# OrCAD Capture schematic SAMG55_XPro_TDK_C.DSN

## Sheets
1 Block Diagram: title: Xpro and TDK-Sensor; rev: C; company: TDK (Invensense); note: Block Diagram; note: 1745 Technology Dr.; note: San Jose, CA 95110
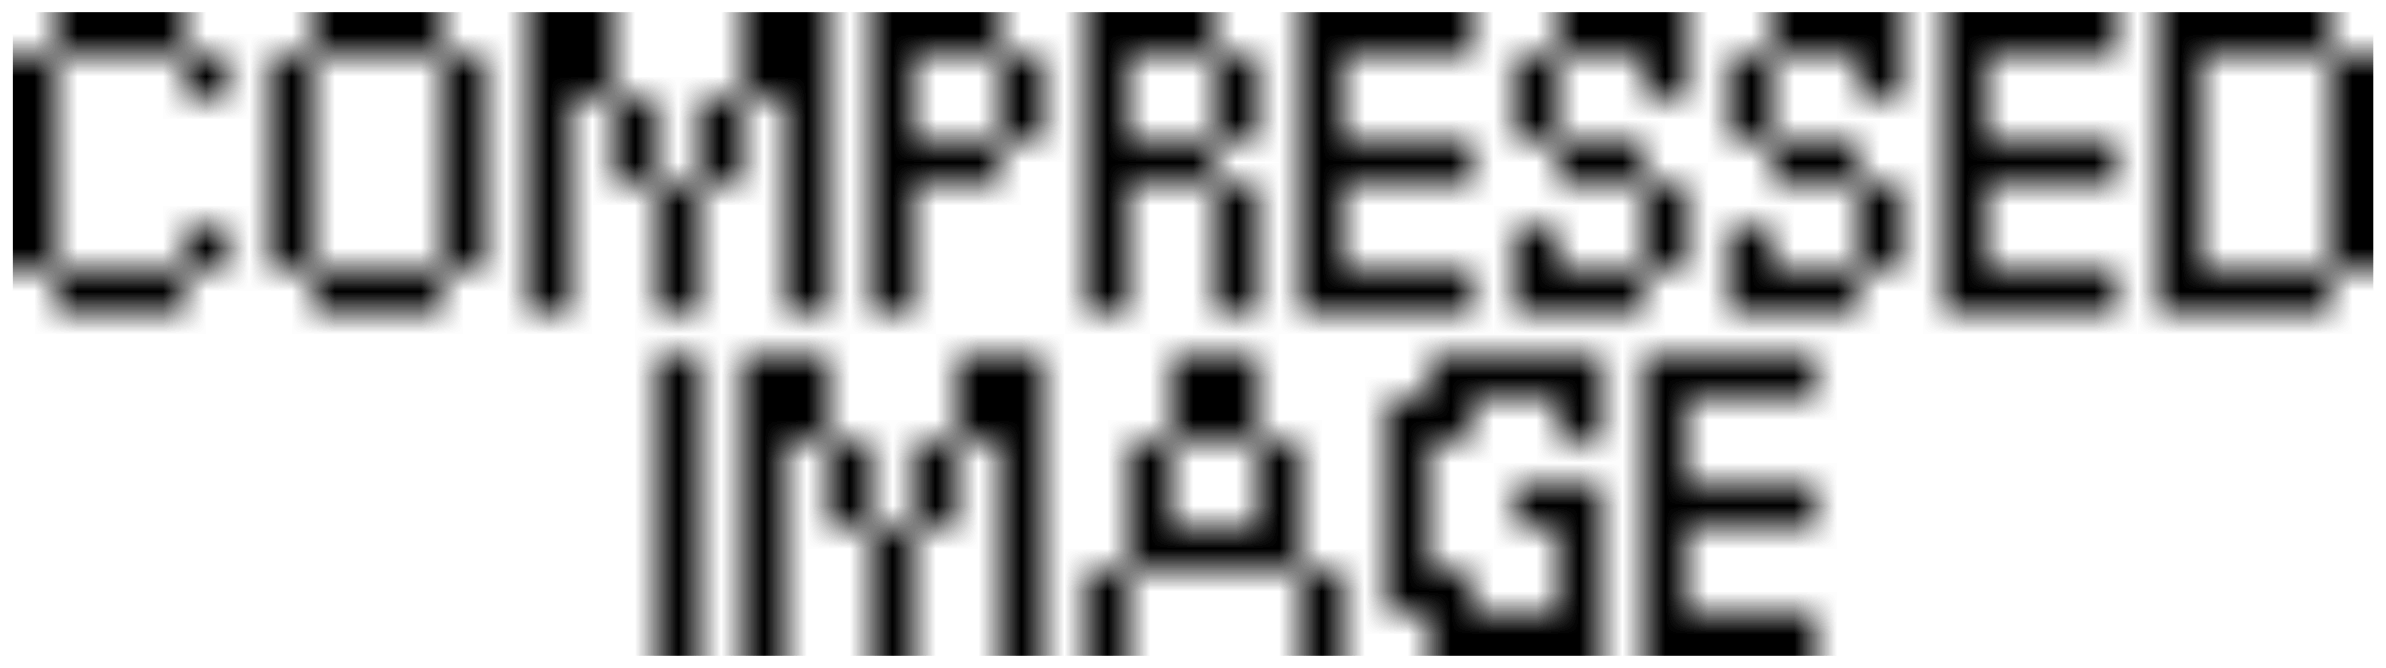
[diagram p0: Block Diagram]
2 TOP: size Custom; note: Top
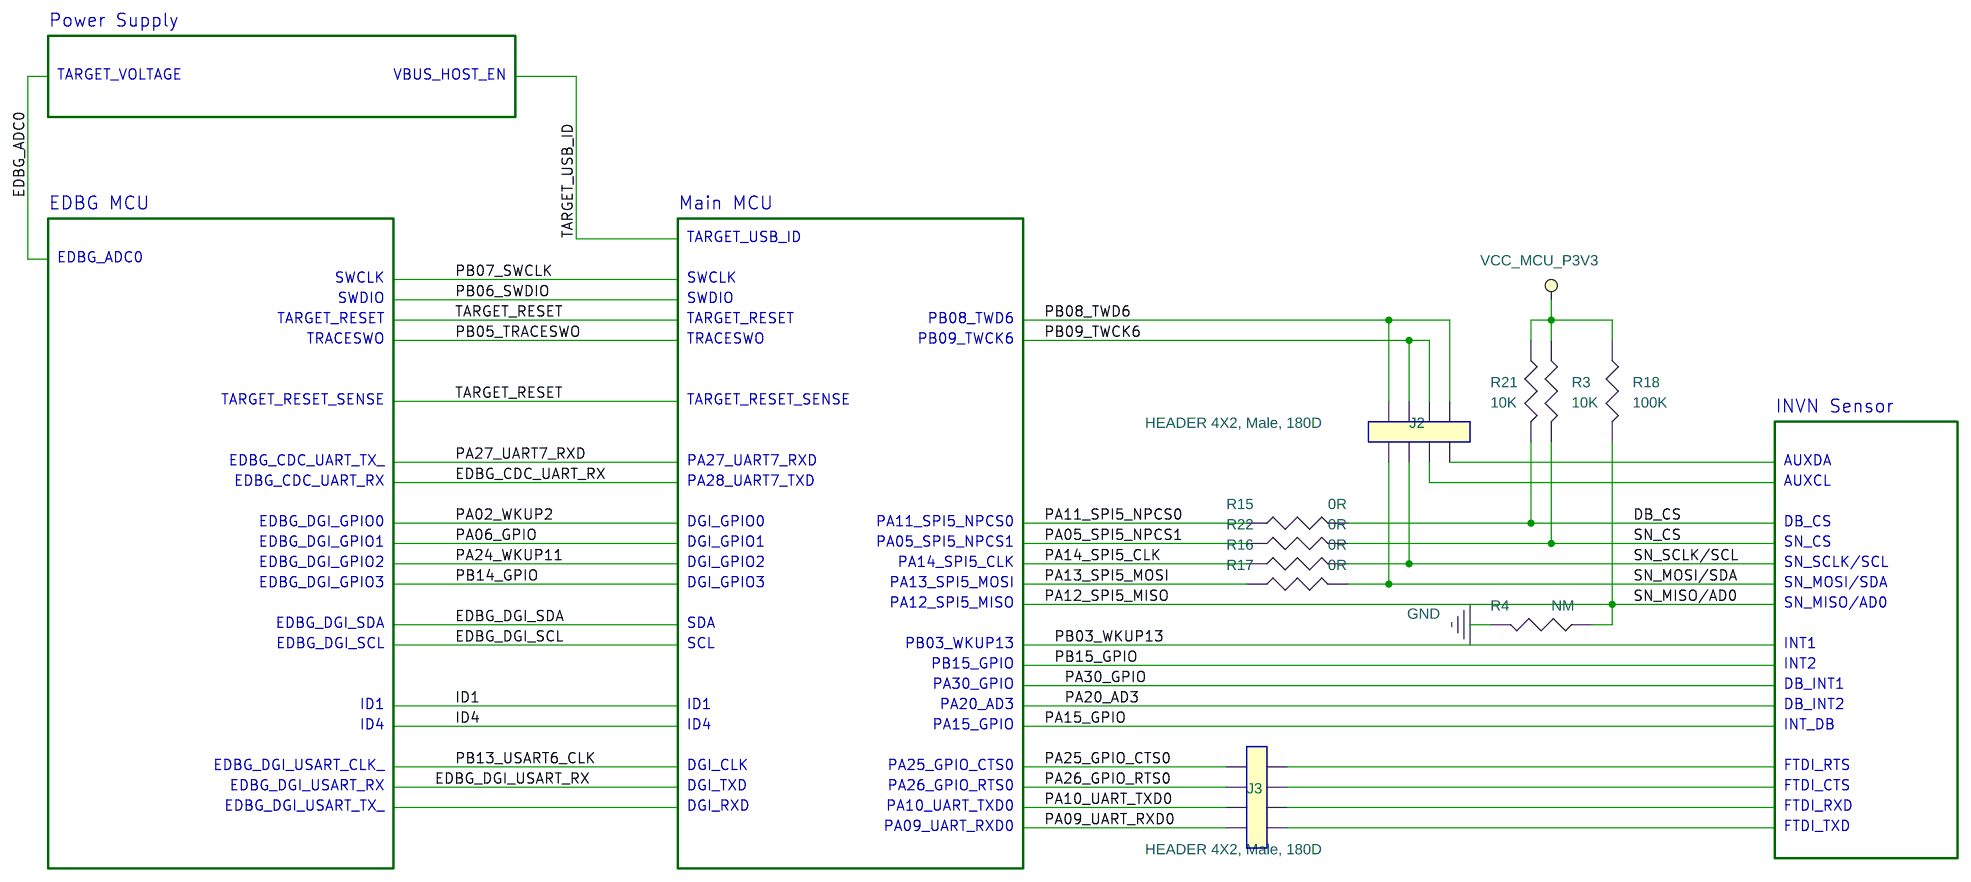
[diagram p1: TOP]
3 EDBG MCU: size Custom; note: EDBG (Embedded Debugger); block EDBG MCU
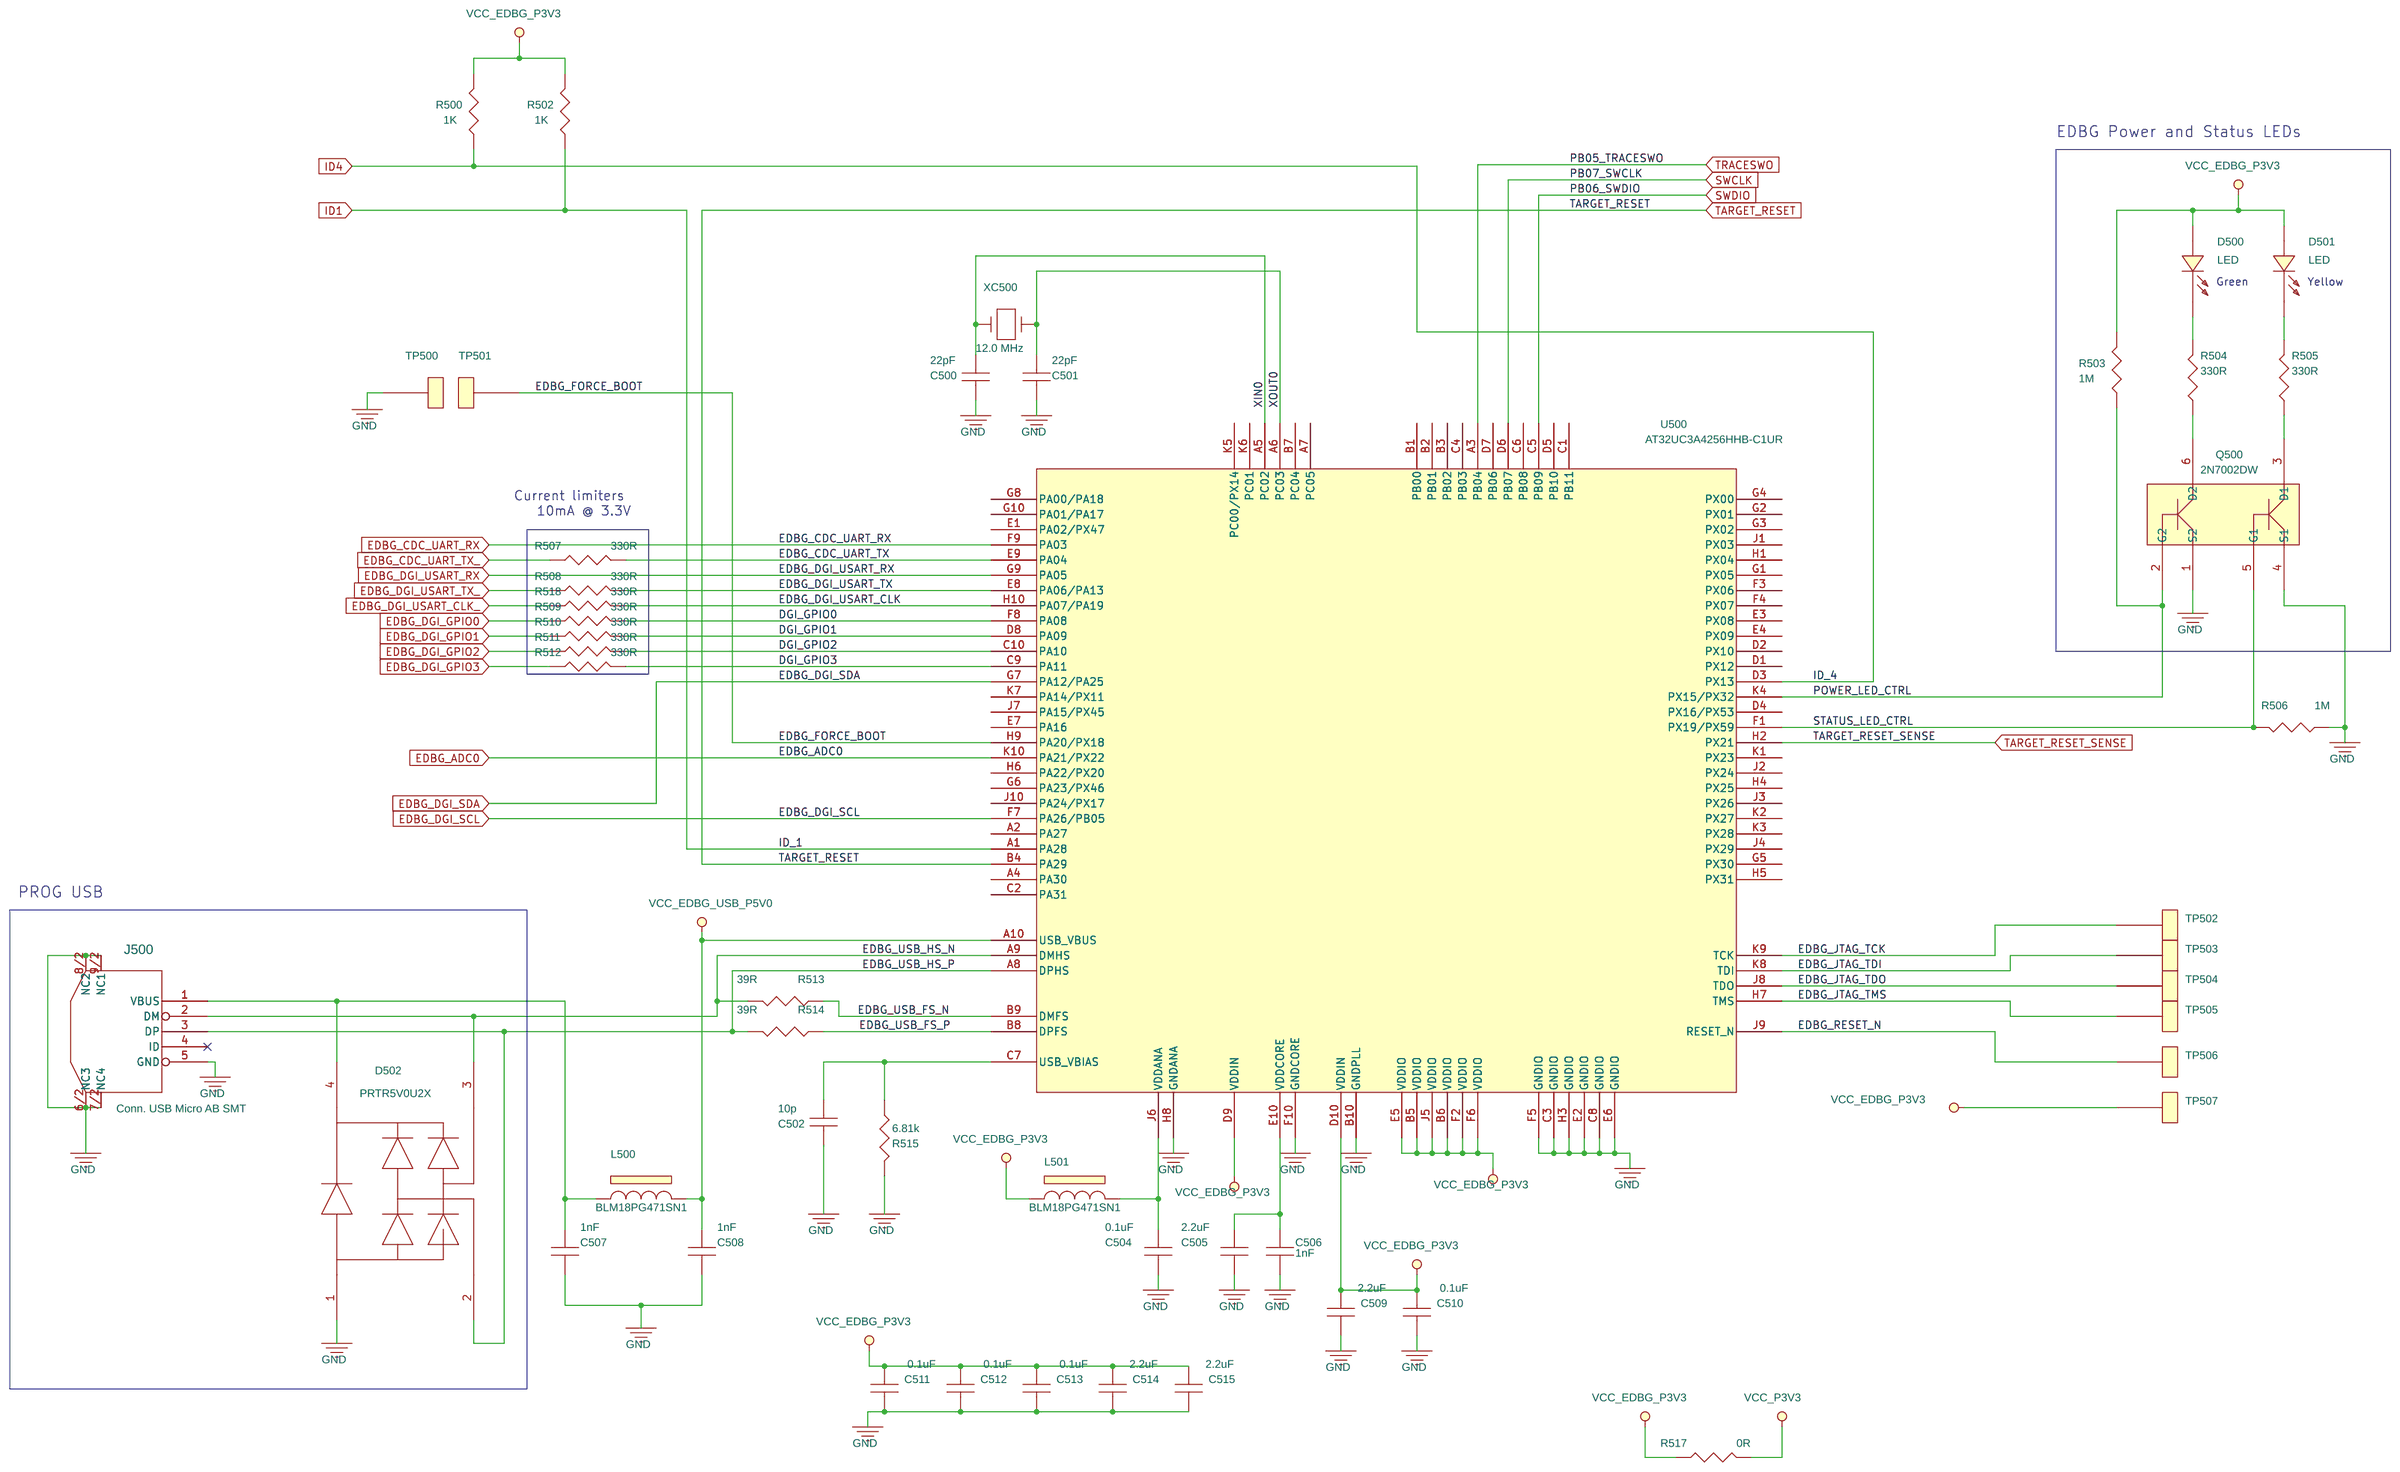
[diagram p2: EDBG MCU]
4 INVN Sensor: size Custom; note: TDK (InvenSense Sensor); block INVN Sensor
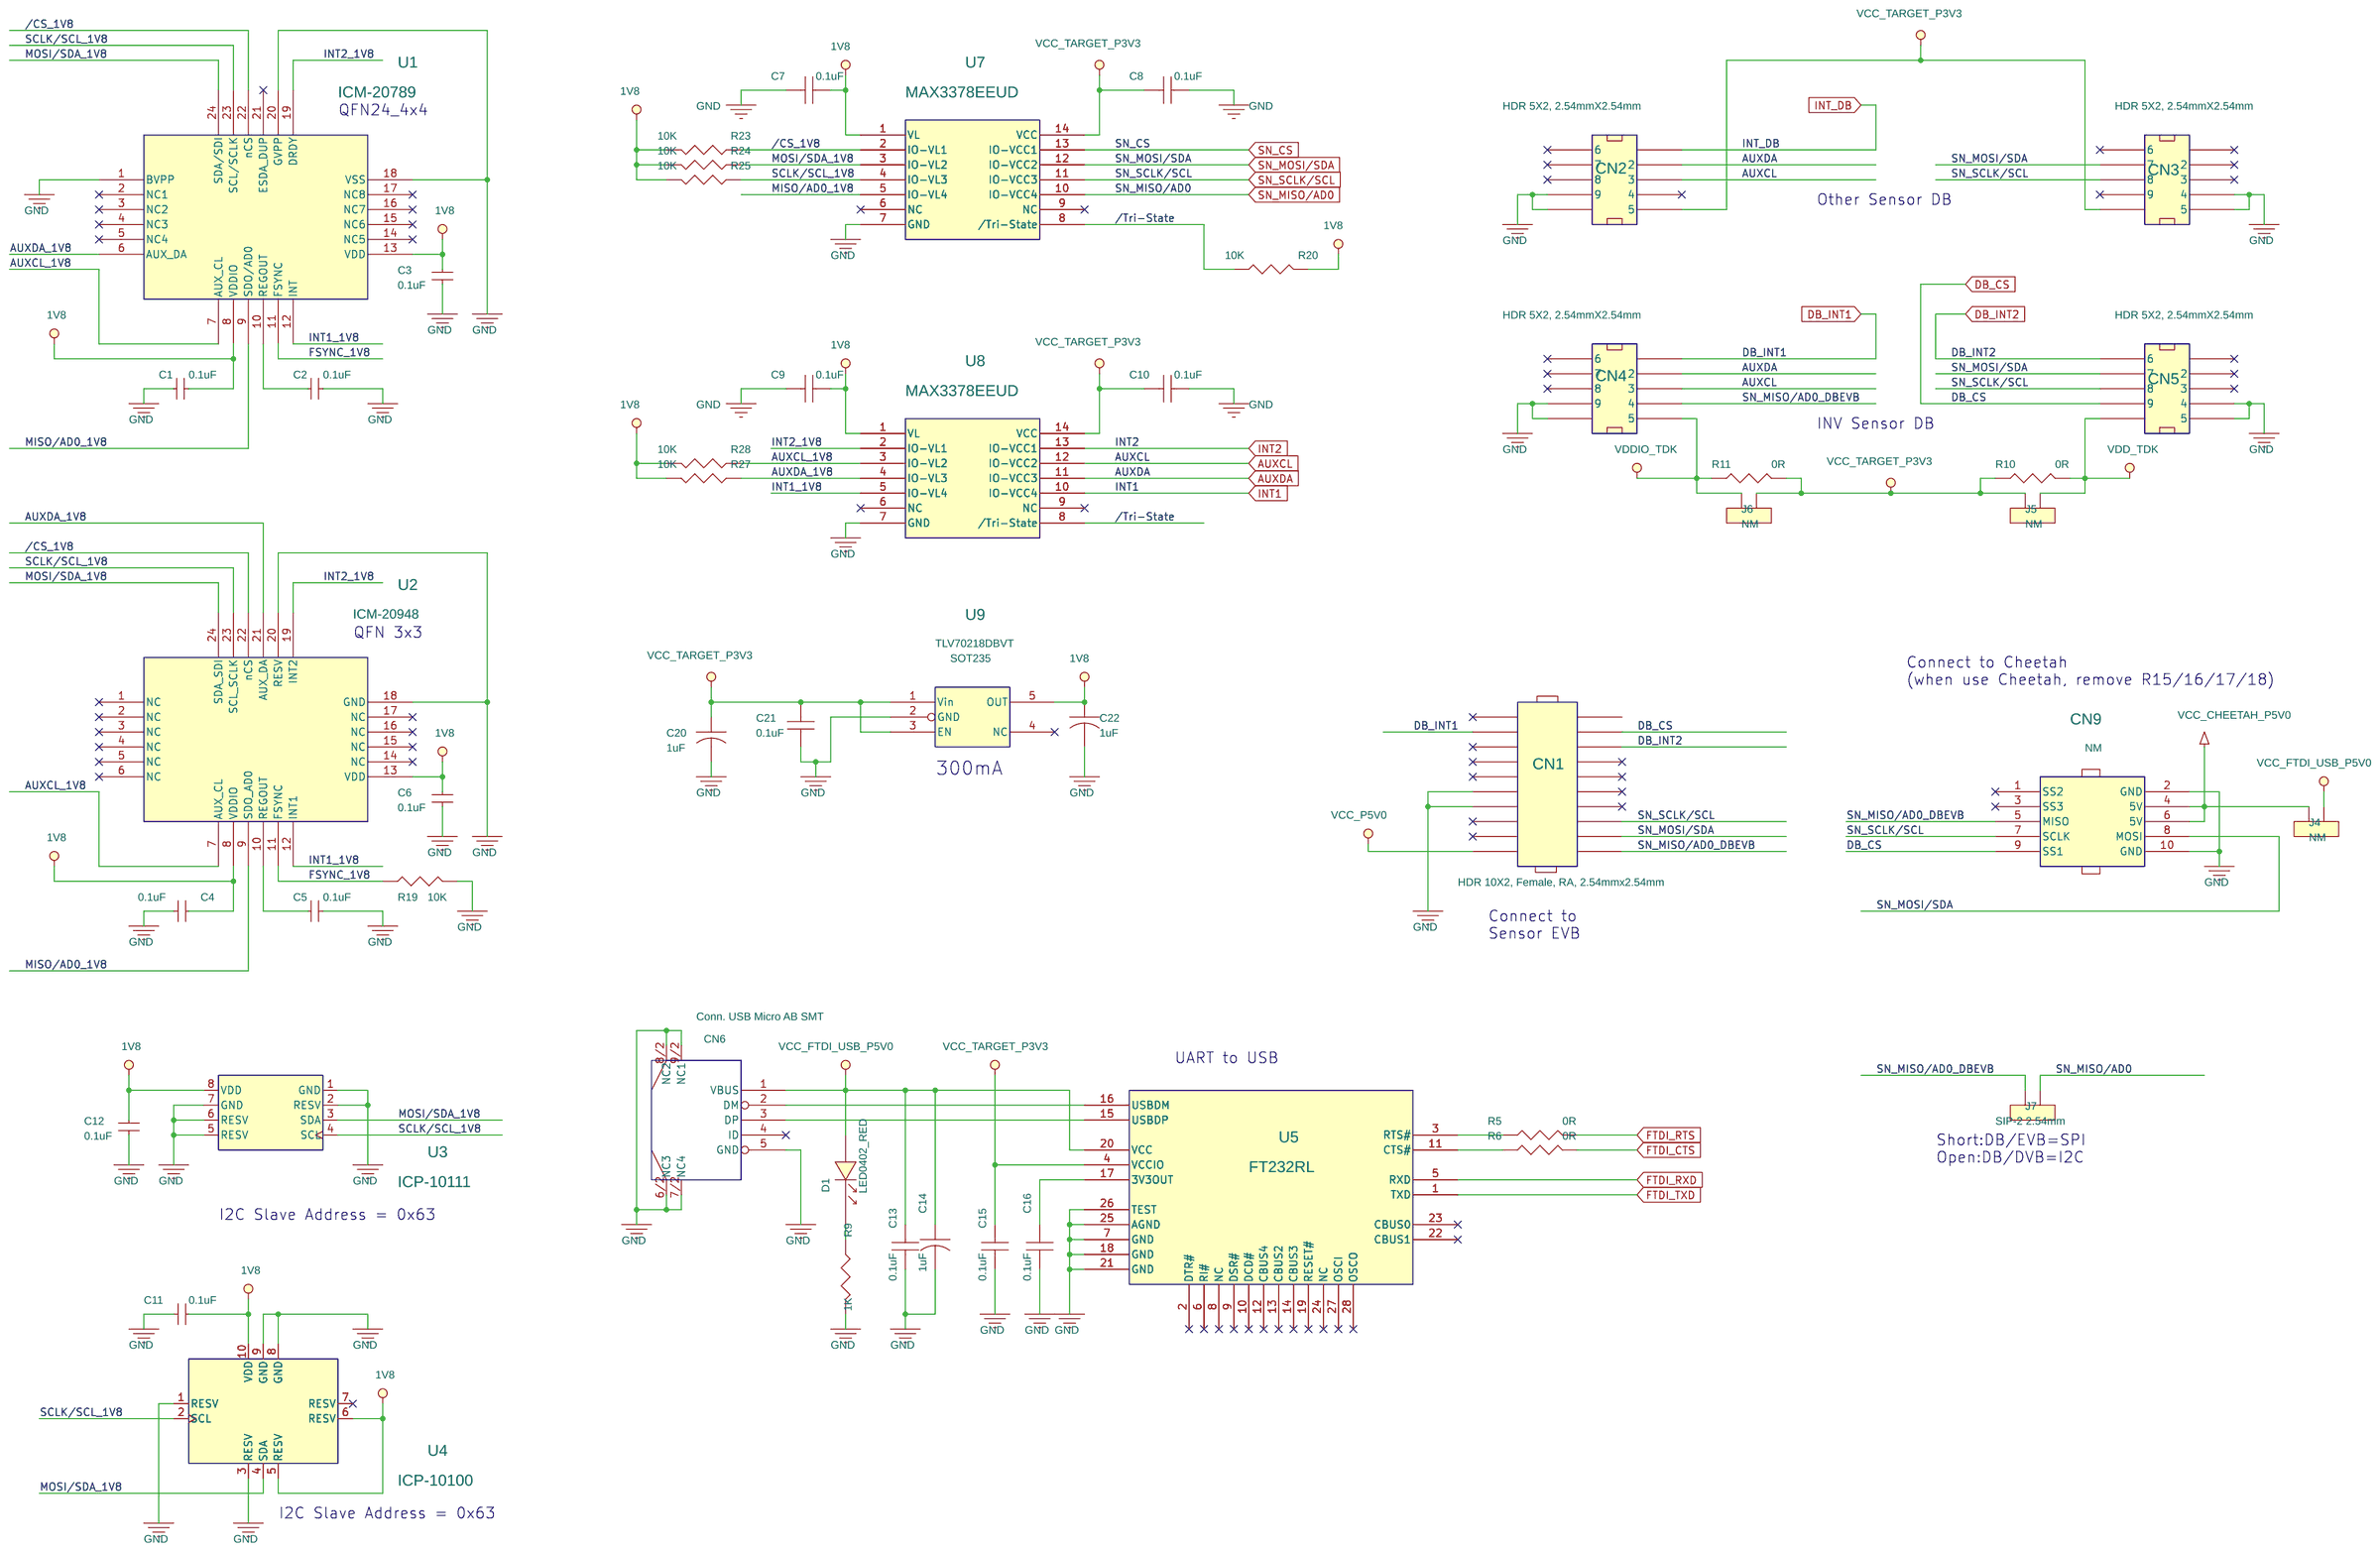
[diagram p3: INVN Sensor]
5 Main MCU: size Custom; note: Main MCU; block Main MCU
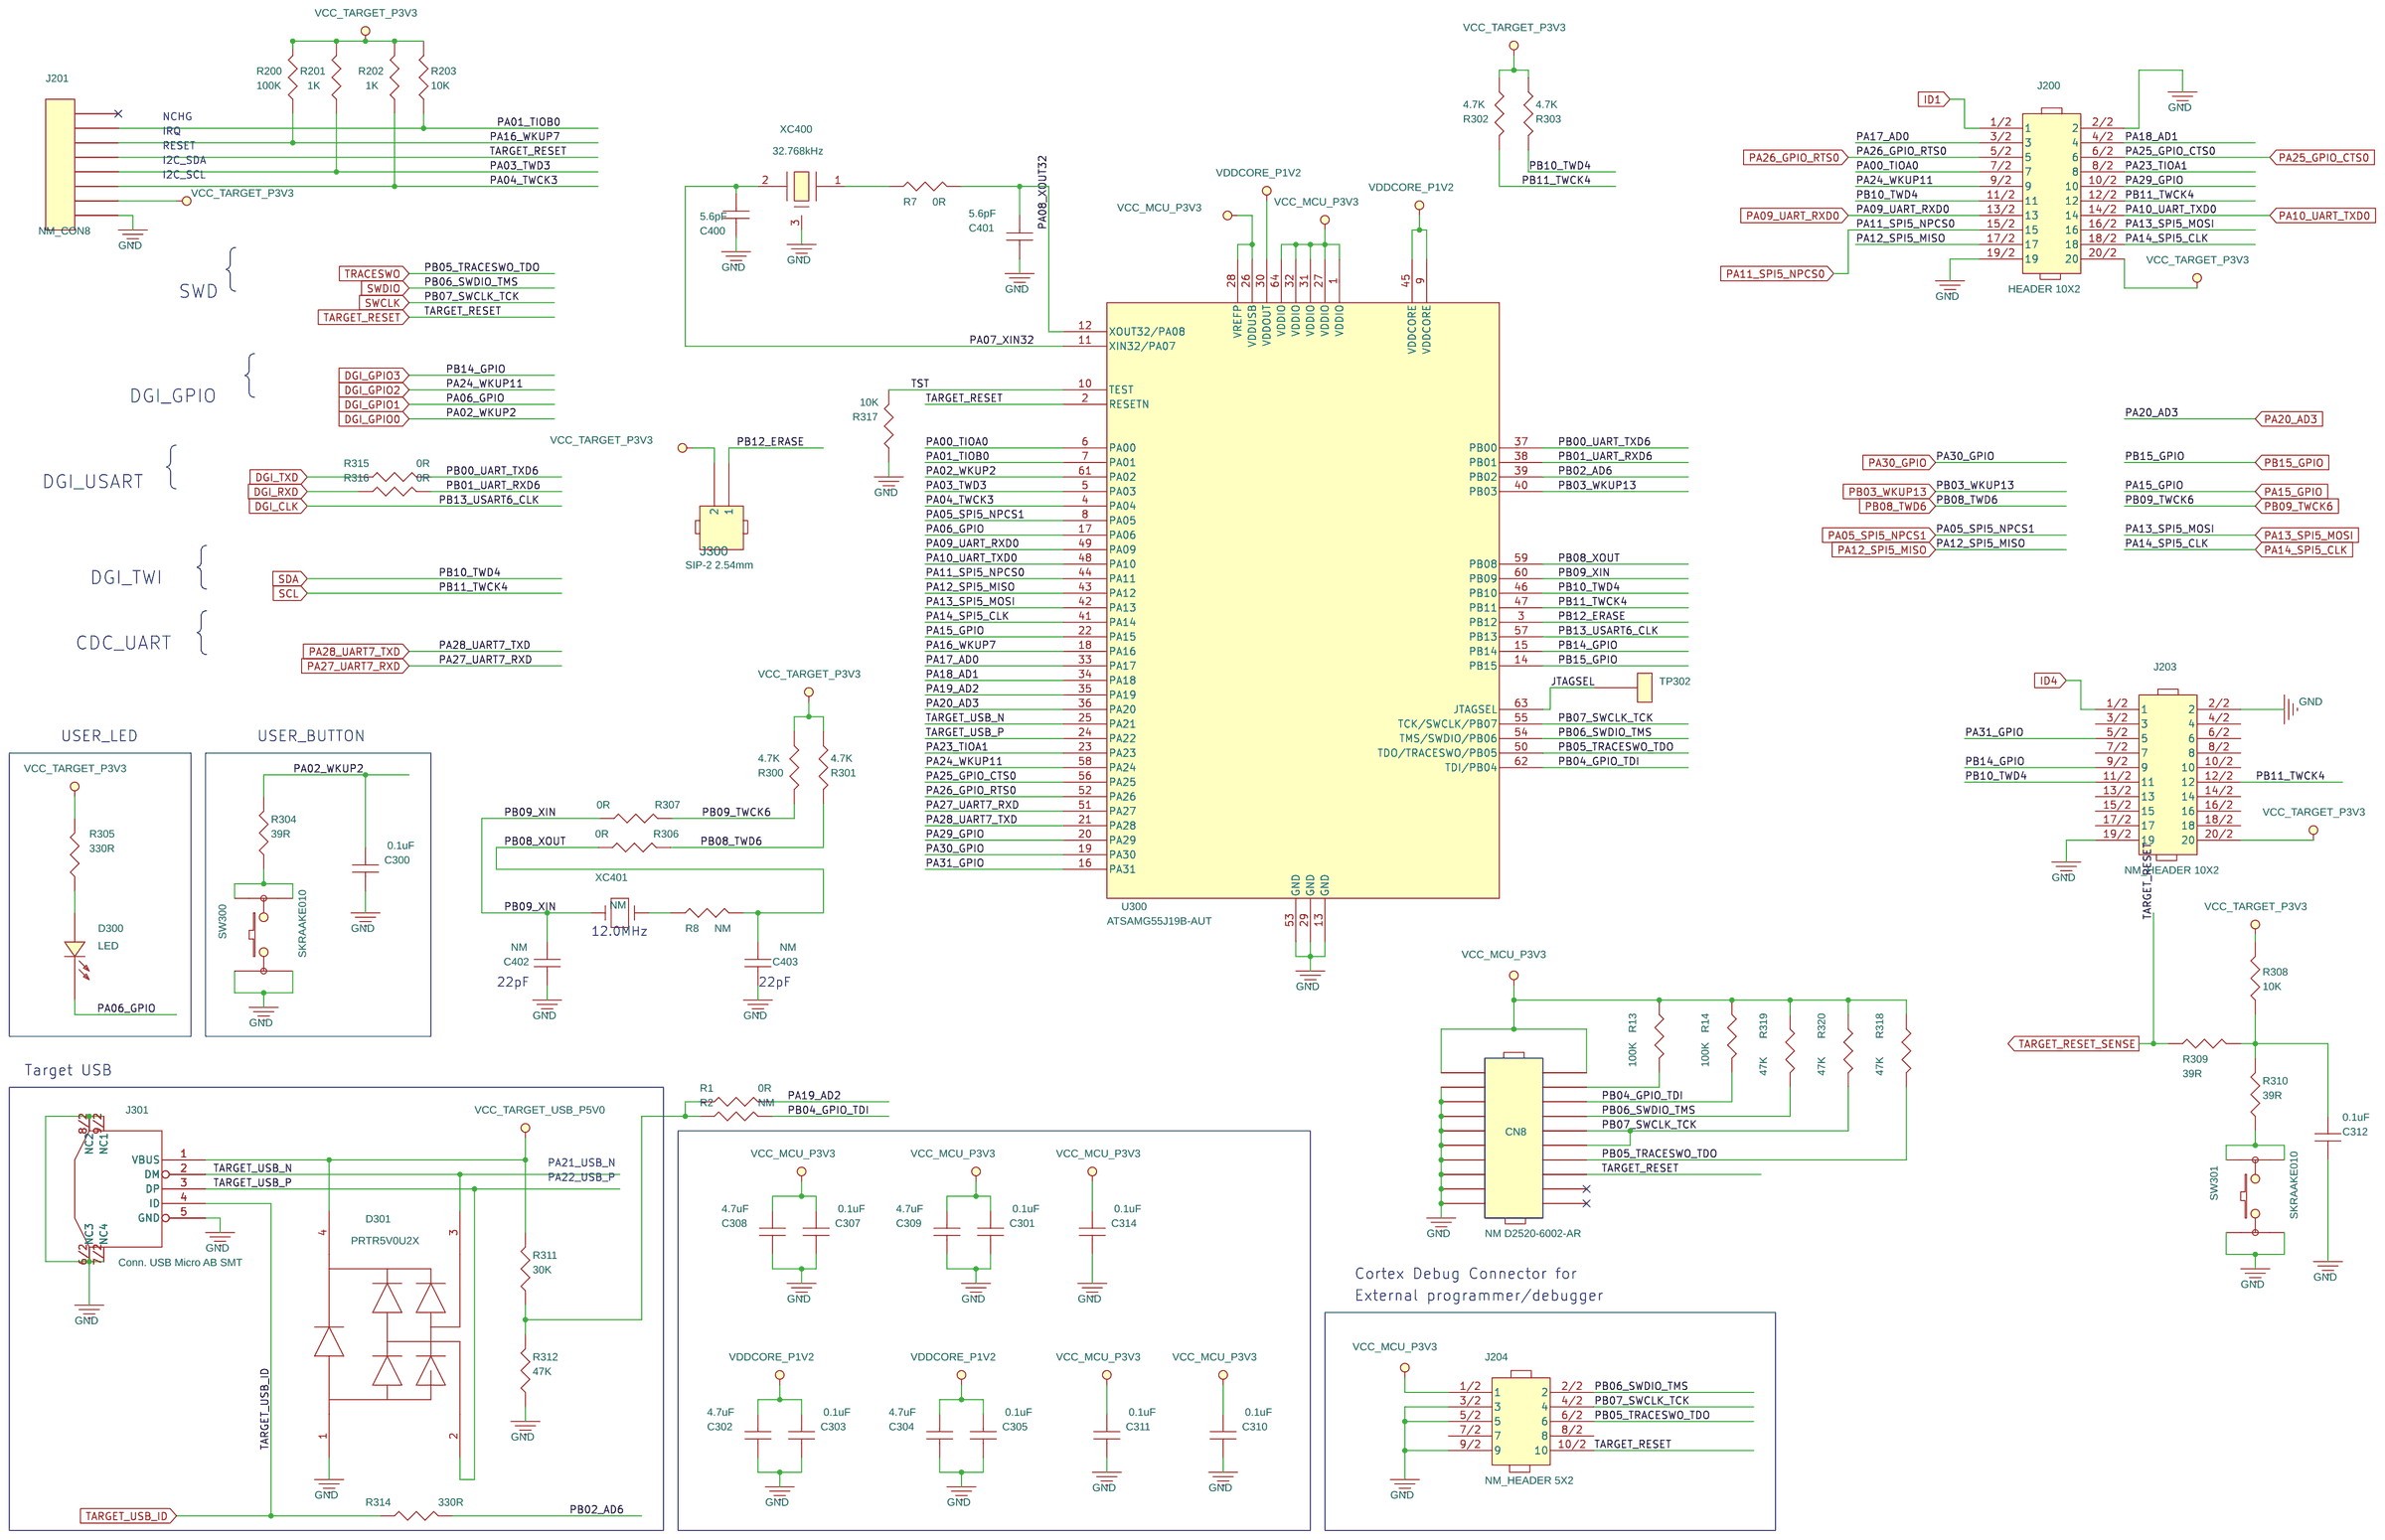
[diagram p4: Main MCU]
6 Power Supply: size Custom; note: Power; block Power Supply
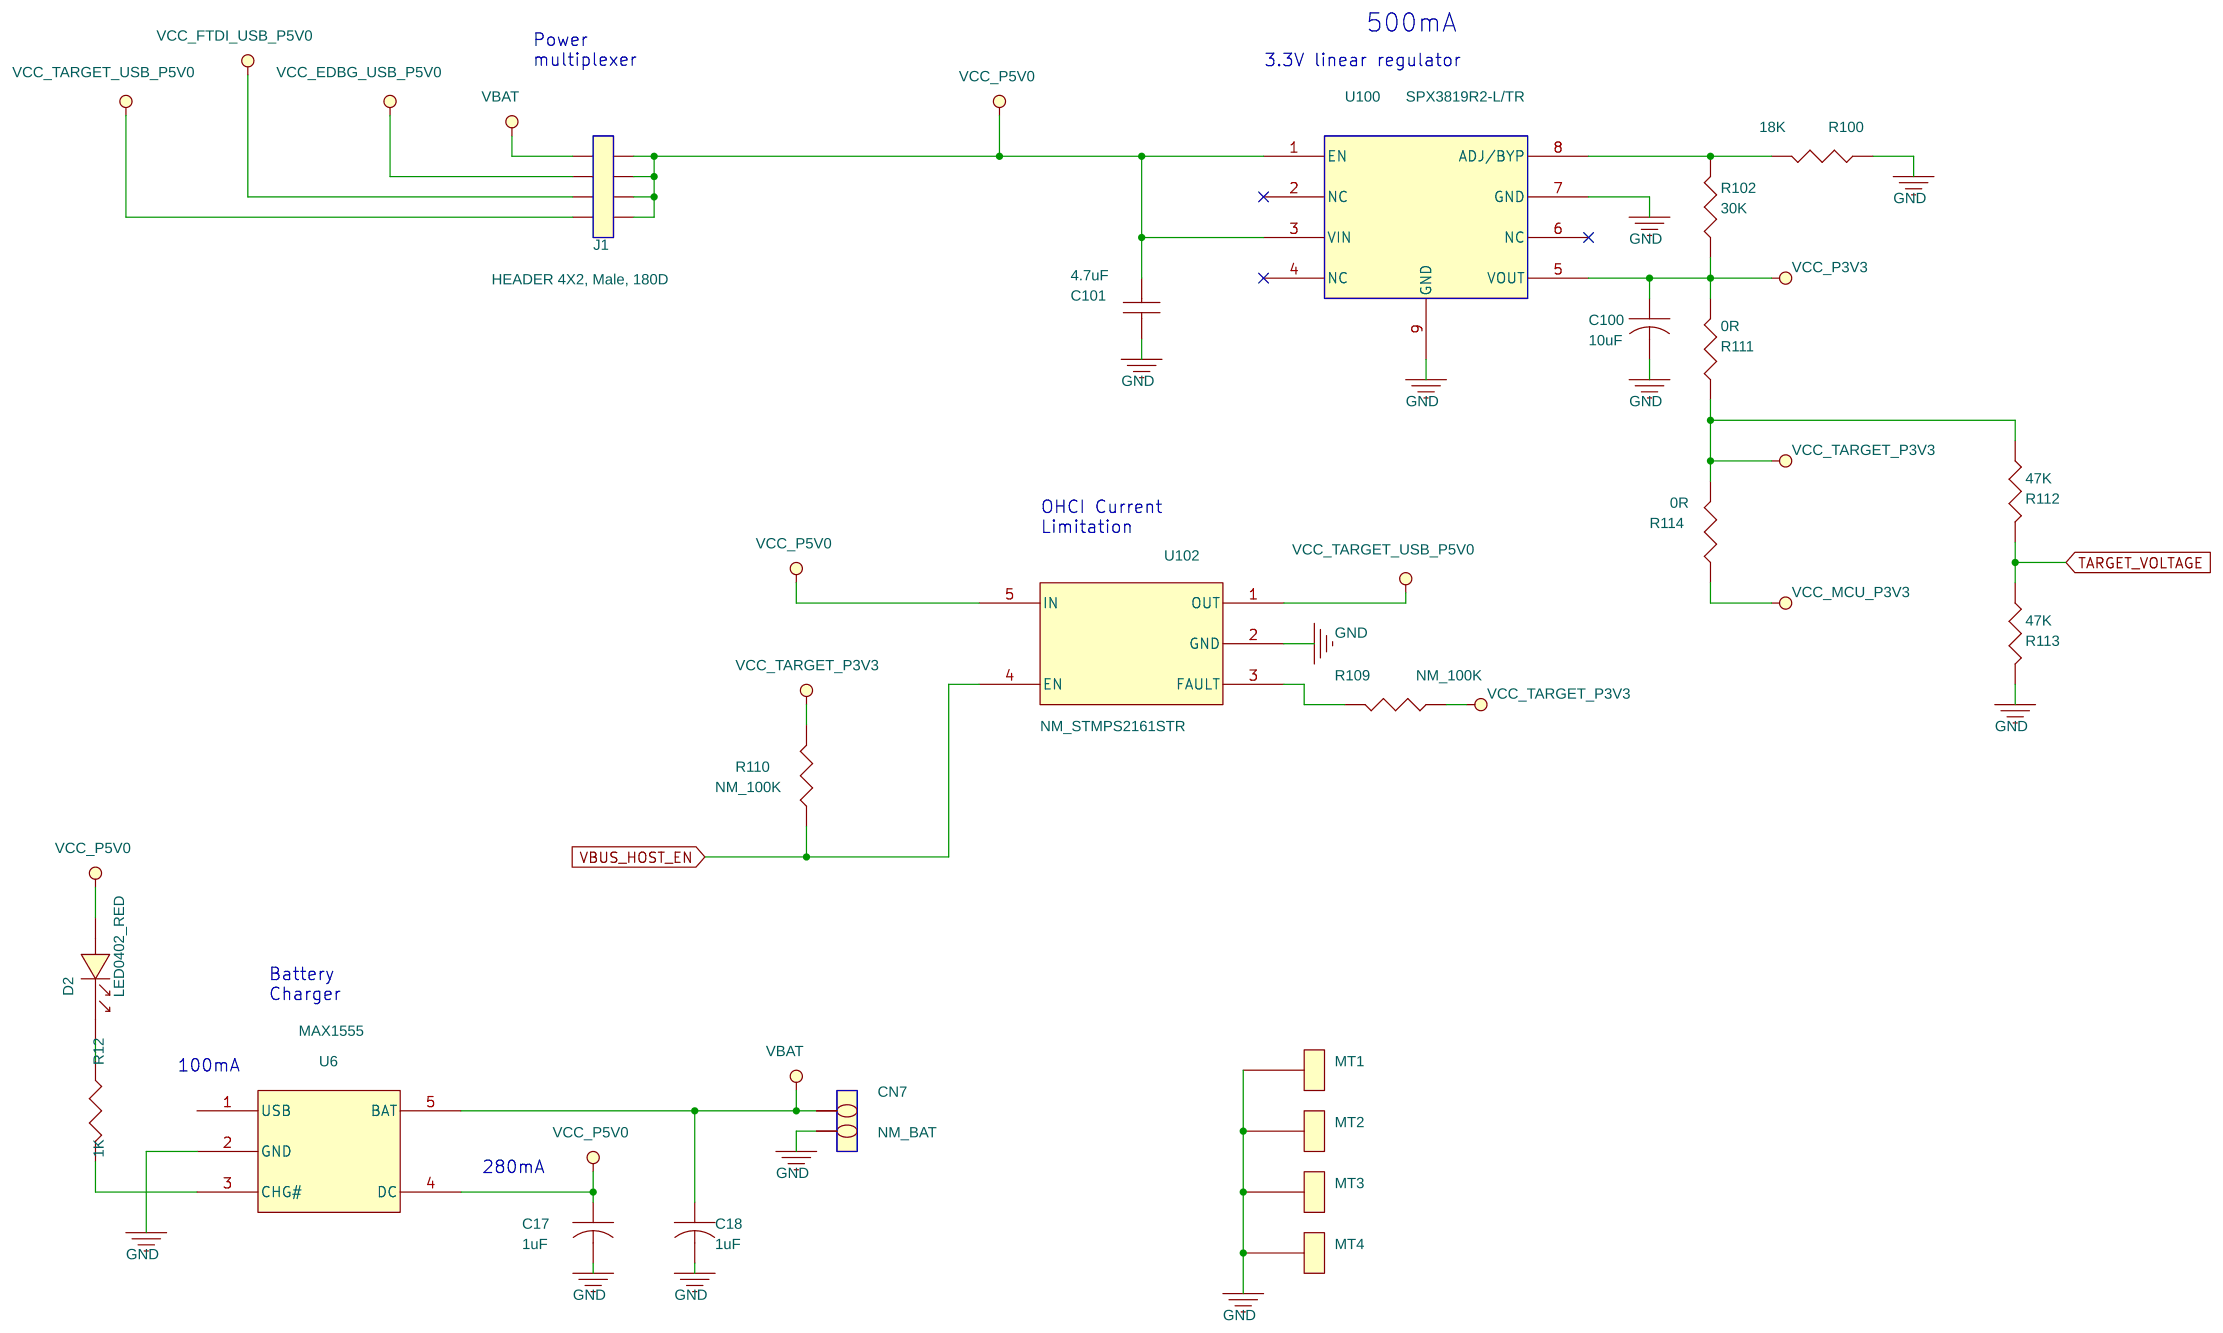
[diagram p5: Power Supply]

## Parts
sheet EDBG MCU
C500  22pF  [C0402]
C501  22pF  [C0402]
C502  10p  [C0402]
C504  0.1uF  [C0402]
C505  2.2uF  [C0402]
C506  1nF  [C0402]
C507  1nF  [C0402]
C508  1nF  [C0402]
C509  2.2uF  [C0402]
C510  0.1uF  [C0402]
C511  0.1uF  [C0402]
C512  0.1uF  [C0402]
C513  0.1uF  [C0402]
C514  2.2uF  [C0402]
C515  2.2uF  [C0402]
D500  LED  [A10-0018]
D501  LED  [A10-0019]
D502  PRTR5V0U2X  [A06-0236]
J500  Conn. USB Micro AB SMT  [A08-2112]
L500  BLM18PG471SN1  [L0603]
L501  BLM18PG471SN1  [L0603]
Q500  2N7002DW  [A05-0051]
R500  1K  [R0402]
R502  1K  [R0402]
R503  1M  [R0402]
R504  330R  [R0402]
R505  330R  [R0402]
R506  1M  [R0402]
R507  330R  [R0402]
R508  330R  [R0402]
R509  330R  [R0402]
R510  330R  [R0402]
R511  330R  [R0402]
R512  330R  [R0402]
R513  39R  [R0402]
R514  39R  [R0402]
R515  6.81k  [R0402]
R517  0R  [R0402]
R518  330R  [R0402]
TP500  TEST POINT  [A08-0004]
TP501  TEST POINT  [A08-0004]
TP502  TEST POINT  [A08-0004]
TP503  TEST POINT  [A08-0004]
TP504  TEST POINT  [A08-0004]
TP505  TEST POINT  [A08-0004]
TP506  TEST POINT  [A08-0004]
TP507  TEST POINT  [A08-0004]
U500  AT32UC3A4256HHB-C1UR  [A06-0736]
XC500  12.0 MHz  [A07-0042/2]
sheet INVN Sensor
C1  0.1uF  [C0402]
C2  0.1uF  [C0402]
C3  0.1uF  [C0402]
C4  0.1uF  [C0402]
C5  0.1uF  [C0402]
C6  0.1uF  [C0402]
C7  0.1uF  [C0402]
C8  0.1uF  [C0402]
C9  0.1uF  [C0402]
C10  0.1uF  [C0402]
C11  0.1uF  [C0402]
C12  0.1uF  [C0402]
C13  0.1uF  [C0402]
C14  1uF  [C0402]
C15  0.1uF  [C0402]
C16  0.1uF  [C0402]
C20  1uF  [C0402]
C21  0.1uF  [C0402]
C22  1uF  [C0402]
CN1  HDR 10X2, Female, RA, 2.54mmx2.54mm  [J100\20DF]
CN2  HDR 5X2, 2.54mmX2.54mm  [HEADER2x5]
CN3  HDR 5X2, 2.54mmX2.54mm  [HEADER2x5]
CN4  HDR 5X2, 2.54mmX2.54mm  [HEADER2x5]
CN5  HDR 5X2, 2.54mmX2.54mm  [HEADER2x5]
CN6  Conn. USB Micro AB SMT  [A08-2112]
CN9  NM  [CON2X5-100MIL]
D1  LED0402_RED  [LED0402]
J4  NM  [sip-2p]
J5  NM  [sip-2p]
J6  NM  [sip-2p]
J7  SIP-2 2.54mm  [sip-2p]
R5  0R  [R0402]
R6  0R  [R0402]
R9  1K  [R0402]
R10  0R  [R0402]
R11  0R  [R0402]
R19  10K  [R0402]
R20  10K  [R0402]
R23  10K  [R0402]
R24  10K  [R0402]
R25  10K  [R0402]
R27  10K  [R0402]
R28  10K  [R0402]
U1  ICM-20789  [QFN24_4X4(0.5PITCH)]
U2  ICM-20948  [LGA24-A_3x3]
U3  ICP-10111  [LGA8_2X2.5]
U4  ICP-10100  [LGA10_2X2]
U5  FT232RL  [SSOP28]
U7  MAX3378EEUD  [TSSOP14]
U8  MAX3378EEUD  [TSSOP14]
U9  TLV70218DBVT  [SOT235]
sheet Main MCU
C300  0.1uF  [C0402]
C301  0.1uF  [C0402]
C302  4.7uF  [C0402]
C303  0.1uF  [C0402]
C304  4.7uF  [C0402]
C305  0.1uF  [C0402]
C307  0.1uF  [C0402]
C308  4.7uF  [C0402]
C309  4.7uF  [C0402]
C310  0.1uF  [C0402]
C311  0.1uF  [C0402]
C312  0.1uF  [C0402]
C314  0.1uF  [C0402]
C400  5.6pF  [C0402]
C401  5.6pF  [C0402]
C402  NM  [C0402]
C403  NM  [C0402]
CN8  NM D2520-6002-AR  [D2520-6002-AR]
D300  LED  [A10-0019]
D301  PRTR5V0U2X  [A06-0236]
J200  HEADER 10X2  [A08-1513]
J201  NM_CON8  [A08-0094]
J203  NM_HEADER 10X2  [A08-1513]
J204  NM_HEADER 5X2  [A08-0385]
J300  SIP-2 2.54mm  [A08-1754]
J301  Conn. USB Micro AB SMT  [A08-2112]
R1  0R  [R0402]
R2  NM  [R0402]
R7  0R  [R0402]
R8  NM  [R0402]
R13  100K  [R0402]
R14  100K  [R0402]
R200  100K  [R0402]
R201  1K  [R0402]
R202  1K  [R0402]
R203  10K  [R0402]
R300  4.7K  [R0402]
R301  4.7K  [R0402]
R302  4.7K  [R0402]
R303  4.7K  [R0402]
R304  39R  [R0402]
R305  330R  [R0402]
R306  0R  [R0402]
R307  0R  [R0402]
R308  10K  [R0402]
R309  39R  [R0402]
R310  39R  [R0402]
R311  30K  [R0402]
R312  47K  [R0402]
R314  330R  [R0402]
R315  0R  [R0402]
R316  0R  [R0402]
R317  10K  [R0402]
R318  47K  [R0402]
R319  47K  [R0402]
R320  47K  [R0402]
SW300  SKRAAKE010  [A08-0790]
SW301  SKRAAKE010  [A08-0790]
TP302  TEST POINT  [A08-0004]
U300  ATSAMG55J19B-AUT  [A06-1153]
XC400  32.768kHz  [A07-0052]
XC401  NM  [A07-0042]
sheet Power Supply
C17  1uF  [C0402]
C18  1uF  [C0402]
C100  10uF  [C0603]
C101  4.7uF  [C0402]
CN7  NM_BAT  [SIP-2_1.27]
D2  LED0402_RED  [LED0402]
J1  HEADER 4X2, Male, 180D  [HEADER2X4]
MT1  TEST POINT  [FPAD_1]
MT2  TEST POINT  [FPAD_1]
MT3  TEST POINT  [FPAD_1]
MT4  TEST POINT  [FPAD_1]
R12  1K  [R0402]
R100  18K  [R0402]
R102  30K  [R0402]
R109  NM_100K  [R0402]
R110  NM_100K  [R0402]
R111  0R  [R0402]
R112  47K  [R0402]
R113  47K  [R0402]
R114  0R  [R0603]
U6  MAX1555  [SOT235]
U100  SPX3819R2-L/TR  [A06-0957]
U102  NM_STMPS2161STR  [A06-1087]
sheet TOP
J2  HEADER 4X2, Male, 180D  [HEADER2X4]
J3  HEADER 4X2, Male, 180D  [HEADER2X4]
R3  10K  [R0402]
R4  NM  [R0402]
R15  0R  [R0402]
R16  0R  [R0402]
R17  0R  [R0402]
R18  100K  [R0402]
R21  10K  [R0402]
R22  0R  [R0402]

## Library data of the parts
C402 C403 C500 C501 = CAP_NP: Manufacturer: TDK; Manufacturer's part number: C1005C0G1H220G050BA; Supplier: Digi-Key; Supplier ref.: 445-5363-1-ND
C502 = CAP_NP: Manufacturer: TDK; Manufacturer's part number: C1005C0G1H100D050BA; Supplier: Digi-Key; Supplier ref.: 445-1235-1-ND
C7-C10 C13 C15 C16 C21 C300 C301 C303 C305 C307 C310-C312 C314 C504 C510-C513 = CAP_NP: Manufacturer: Yageo; Manufacturer's part number: CC0402KRX5R6BB104; Supplier: Digi-Key; Supplier ref.: 311-1336-1-ND
C505 C509 C514 C515 = CAP_NP: Manufacturer: TDK; Manufacturer's part number: C1005X5R0J225K050BC; Supplier: Digi-Key; Supplier ref.: 445-6847-1-ND
C506-C508 = CAP_NP: Manufacturer: TDK; Manufacturer's part number: C1005C0G1H102F050BA; Supplier: Digi-Key; Supplier ref.: 445-7023-1-ND
D500 = LED: Manufacturer: Everlight; Manufacturer's part number: 17-21SYGC/S530-E2/TR8; Supplier: Mouser; Supplier ref.: 638-1721SYGCS530E2
D300 D501 = LED: Manufacturer: Everlight; Manufacturer's part number: QTLP630C3TR; Supplier: Digi-Key; Supplier ref.: 1080-1410-1-ND
D301 D502 = PRTR5V0U2X: Manufacturer: Nexperia; Manufacturer's part number: PRTR5V0U2X,215; Supplier: Digi-Key; Supplier ref.: 1727-3884-1-ND
CN6 J301 J500 = USB_Con_B_0: Manufacturer: Hirose; Manufacturer's part number: ZX62D-AB-5P8(30); Supplier: Digi-Key; Supplier ref.: H125271CT-ND
L500 L501 = INDUCTOR_FERRITE: Manufacturer: Murata; Supplier: Digi-Key; Supplier ref.: 490-5223-1-ND
Q500 = 2N7002DW_0: Manufacturer: Diodes; Manufacturer's part number: 2N7002DW-7-F; Supplier: Digi-Key; Supplier ref.: 2N7002DW-FDICT-ND
R201 R202 R500 R502 = R: Manufacturer: Yageo; Manufacturer's part number: RC0402FR-071KL; Supplier: Digi-Key; supplier ref.: 311-1.00KLRCT-ND
R503 R506 = R: Manufacturer: Yageo; Manufacturer's part number: RC0402FR-071ML; Supplier: Digi-Key; supplier ref.: 311-1.00MLRCT-ND
R305 R314 R504 R505 R507-R512 R518 = R: Manufacturer: Yageo; Manufacturer's part number: RC0402FR-07330RL; Supplier: Digi-Key; Supplier ref.: 311-330LRCT-ND
R304 R309 R310 R513 R514 = R: Manufacturer: Yageo; Manufacturer's part number: RC0402FR-0739RL; Supplier: Digi-Key; Supplier ref.: 311-39.0LRTR-ND
R515 = R: Manufacturer: Yageo; Manufacturer's part number: RC0402FR-076K81L; Supplier: Digi-Key; Supplier ref.: 311-6.81KLRCT-ND
R1 R2 R5-R8 R10 R11 R15-R17 R22 R111 R306 R307 R315 R316 R517 = R: Manufacturer: Yageo; Manufacturer's part number: RC0402JR-070RL; Supplier: Digi-Key; Supplier ref.: 311-0.0JRCT-ND
TP302 TP500-TP507 = TEST_POINT: Manufacturer's part number: xx; Supplier: xx; supplier ref.: xx
U500 = AT32UC3A4256J_0: Manufacturer: MicroChip; Supplier: MicroChip
XC401 XC500 = CRYSTAL13: Manufacturer: Fox Electronics; Manufacturer's part number: FQ5032B-12.000; Supplier: Digi-Key; Supplier ref.: 631-1023-1-ND
C1-C6 C11 C12 = CAP_0: Manufacturer: Yageo; Manufacturer's part number: CC0402KRX5R6BB104; Supplier: Digi-Key; supplier ref.: 311-1336-1-ND
C14 C17 C18 C20 C22 = CAP: Manufacturer: Yageo; Manufacturer's part number: CC0402KRX5R6BB105; Supplier: Digi-Key; Supplier ref.: 311-1439-1-ND
CN1 = HEADER_10X2: Manufacturer: Sullins; Manufacturer's part number: PPPC102LJBN-RC; Supplier: Digi-key; Supplier ref.: S5563-ND
CN2-CN5 = CONN_SOCKET_5x2: Manufacturer: FCI; Manufacturer's part number: 67997-210HLF; Supplier: Digi-Key; Supplier ref.: 609-3236-ND
CN9 = CONN_PCB_5x2_3: Manufacturer: FCI; Manufacturer's part number: 67997-210HLF; Supplier: Digi-Key; Supplier ref.: 609-3236-ND
D1 D2 = LED_2: Manufacturer: Kingbright; Manufacturer's part number: APHHS1005SURCK; Supplier: Digi-Key; Supplier ref.: 754-1104-1-ND
J4 = HEADER_2_3: Manufacturer: xx; Manufacturer's part number: xx; Supplier: xx; Supplier ref.: xx
J5 = HEADER_2_4: Manufacturer: xx; Manufacturer's part number: xx; Supplier: xx; Supplier ref.: xx
J6 = HEADER_2_5: Manufacturer: xx; Manufacturer's part number: xx; Supplier: xx; Supplier ref.: xx
J7 = HEADER_2_4: Manufacturer: 3M; Manufacturer's part number: 961102-6404-AR; Supplier: Digi-Key; Supplier ref.: 3M9447-ND
R9 R12 = R: Manufacturer: Yageo; Manufacturer's part number: RC0402FR-071KL; Supplier: Digi-Key; Supplier ref.: 311-1.00KLRCT-ND
R19 R20 R23-R25 R27 R28 = R: Manufacturer: Yageo; Manufacturer's part number: RC0402JR-0710KL; Supplier: Digi-Key; Supplier ref.: 311-10KJRCT-ND
U1 = Madrid: Manufacturer: TDK; Supplier: TDK
U2 = ICM-20700_2: Manufacturer: TDK; Supplier: TDK
U3 = BMP280_0: Manufacturer: TDK; Supplier: TDK
U4 = BMP280_1: Manufacturer: TDK; Supplier: TDK
U5 = FT232RL_11: Manufacturer: FTDI; Manufacturer's part number: FT232RL-REEL; Supplier: Digi-Key; Supplier ref.: 768-1007-1-ND
U7 U8 = MAX3378EEUD_0: Manufacturer: Maxim; Manufacturer's part number: MAX3378EEUD+; Supplier: Digi-Key; Supplier ref.: MAX3378EEUD+-ND
U9 = SEMTECH1_0: Manufacturer: TI; Supplier: Digi-Key; Supplier ref.: 296-27889-1-ND
C101 C302 C304 C308 C309 = CAP_NP: Manufacturer: Samsung; Manufacturer's part number: CL05A475MP5NRNC; Supplier: Digi-Key; Supplier ref.: 1276-1482-1-ND
C400 C401 = CAP_NP: Manufacturer: Murata; Manufacturer's part number: GRM1555C1H5R6CA01D; Supplier: Digi-Key; Supplier ref.: 490-6250-1-ND
CN8 = HEADER_10X2: Manufacturer: 3M; Supplier: Mouser; Supplier ref.: 517-D2520-6002-AR
J200 J203 = HEADER_10X2_0: Manufacturer: TE; Manufacturer's part number: 1-826634-0; Supplier: Mouser; Supplier ref.: 571-1-826634-0
J201 = CON8: Manufacturer: TE; Manufacturer's part number: 3-644456-8; Supplier: Digi-Key; supplier ref.: A31118-ND
J204 = HEADER_5X2_0: Manufacturer's part number: xx; Supplier: xx; supplier ref.: xx
J300 = HEADER_2_0: Manufacturer: 3M; Manufacturer's part number: 961102-6404-AR; Supplier: Digi-Key; Supplier ref.: 3M9447-ND
R13 R14 R109 R110 R200 = R: Manufacturer: Yageo; Manufacturer's part number: RC0402FR-07100KL; Supplier: Digi-Key; supplier ref.: 311-100KLRCT-ND
R203 R308 R317 = R: Manufacturer: Yageo; Manufacturer's part number: RC0402JR-0710KL; Supplier: Digi-Key; supplier ref.: 311-10KJRCT-ND
R300-R303 = R: Manufacturer: Yageo; Manufacturer's part number: RC0402FR-074K7L; Supplier: Digi-Key; Supplier ref.: 311-4.7KLRTR-ND
R102 R311 = R: Manufacturer: Yageo; Manufacturer's part number: RC0402FR-0730KL; Supplier: Digi-Key; Supplier ref.: 311-30.0KLRCT-ND
R312 = R: Manufacturer: Yageo; Manufacturer's part number: RC0402FR-0747KL; Supplier: Digi-Key; Supplier ref.: 311-47.0KLRTR-ND
R112 R113 R318-R320 = R: Manufacturer: Yageo; Manufacturer's part number: RC0402FR-0747KL; Supplier: Digi-Key; supplier ref.: 311-47.0KLRTR-ND
SW300 SW301 = SW_TACT-SPST-2: Manufacturer: ALPS; Supplier: Mouser; Supplier ref.: 688-SKRAAK
U300 = ATSAMG55_0: Manufacturer: Microchi/Atmel; Supplier: Mouser; Supplier ref.: 556-ATSAMG55J19B-AUT
XC400 = Crystal-3pin: Manufacturer: Diodes; Manufacturer's part number: G33270010; Supplier: Digi-Key; Supplier ref.: G33270010DKR-ND
C100 = CAP: Manufacturer: Murata; Manufacturer's part number: GRM188R61A106KE69D; Supplier: Digi-Key; Supplier ref.: 490-10474-1-ND
CN7 = 8_HEADER_0: Manufacturer: SCS; Manufacturer's part number: GRPB021VWVN-RC; Supplier: Digi-Key; Supplier ref.: S9014E-02-ND
J1 = HEADER_4X2_0: Manufacturer: Samtec; Manufacturer's part number: TSW-104-08-G-D; Supplier: Digi-key; Supplier ref.: SAM1036-04-ND
MT1-MT4 = TEST_POINT: Manufacturer's part number: xx; Supplier: xx; Supplier ref.: xx
R100 = R: Manufacturer: Yageo; Manufacturer's part number: RC0402JR-0718KL; Supplier: Digi-Key; Supplier ref.: 311-18KJRCT-ND
R114 = R: Manufacturer: Stackpole; Manufacturer's part number: HCJ0603ZT0R00; Supplier: Digi-Key; Supplier ref.: HCJ0603ZT0R00CT-ND
U6 = MAX1555_0: Manufacturer: Maxim; Manufacturer's part number: MAX1555EZK+T; Supplier: Digi-Key; Supplier ref.: MAX1555EZK+TCT-ND
U100 = SPX3819R2-L_TR: Manufacturer: Exar; Supplier: Digi-Key; Supplier ref.: 1016-1588-1-ND
U102 = STMPS2161STR: Manufacturer: ST; Supplier: Digi-Key; Supplier ref.: 497-6936-1-ND
J2 J3 = HEADER_4X2_0: Manufacturer: Samtec; Manufacturer Part Number: TSW-104-08-G-D; Manufacturer's part number: TSW-104-08-G-D; Supplier: Digi-key; Supplier ref.: SAM1036-04-ND
R3 R21 = R: Manufacturer: Yageo; Manufacturer Part Number: RC0402FR-0710KL; Manufacturer's part number: RC0402JR-0710KL; Supplier: Digi-Key; Supplier ref.: 311-10KJRCT-ND; supplier part number: 311-10.0KLRCT-ND
R4 R18 = R: Manufacturer: Yageo; Manufacturer Part Number: RC0402FR-07100KL; Manufacturer's part number: RC0402FR-07100KL; Supplier: Digi-Key; supplier ref.: 311-100KLRCT-ND

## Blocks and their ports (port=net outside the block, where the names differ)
INVN Sensor = schematic 4. INVN Sensor, on sheet TOP: SN_CS, SN_SCLK/SCL, SN_MOSI/SDA, SN_MISO/AD0=PA12_SPI5_MISO, INT1=PB03_WKUP13, INT2=PB15_GPIO, DB_INT1=PA30_GPIO, INT_DB=PA15_GPIO, AUXDA=N96210, AUXCL=N96214, FTDI_RXD=N115091, FTDI_TXD=N115089, FTDI_CTS=N115093, FTDI_RTS=N115095, DB_CS, DB_INT2=PA20_AD3
Main MCU = schematic 1. Main MCU, on sheet TOP: TRACESWO=PB05_TRACESWO, SWDIO=PB06_SWDIO, SWCLK=PB07_SWCLK, TARGET_RESET, DGI_GPIO0=PA02_WKUP2, TARGET_RESET_SENSE=TARGET_RESET, DGI_GPIO1=PA06_GPIO, DGI_GPIO2=PA24_WKUP11, DGI_CLK=PB13_USART6_CLK, SDA=EDBG_DGI_SDA, SCL=EDBG_DGI_SCL, PA28_UART7_TXD=EDBG_CDC_UART_RX, PA27_UART7_RXD, TARGET_USB_ID, ID1, ID4, PA12_SPI5_MISO, PA05_SPI5_NPCS1, PB08_TWD6, PA14_SPI5_CLK, PA13_SPI5_MOSI, PB09_TWCK6, PB03_WKUP13, PB15_GPIO, PA30_GPIO, PA26_GPIO_RTS0, DGI_TXD=EDBG_DGI_USART_RX, PA25_GPIO_CTS0, PA15_GPIO, PA09_UART_RXD0, PA10_UART_TXD0, DGI_RXD=N105398, DGI_GPIO3=PB14_GPIO, PA11_SPI5_NPCS0, PA20_AD3
EDBG MCU = schematic 2. EDBG MCU, on sheet TOP: TARGET_RESET_SENSE=TARGET_RESET, SWDIO=PB06_SWDIO, SWCLK=PB07_SWCLK, TARGET_RESET, TRACESWO=PB05_TRACESWO, EDBG_DGI_GPIO0=PA02_WKUP2, EDBG_DGI_GPIO1=PA06_GPIO, EDBG_DGI_GPIO2=PA24_WKUP11, EDBG_DGI_USART_RX, EDBG_DGI_USART_TX_=N105398, EDBG_DGI_USART_CLK_=PB13_USART6_CLK, EDBG_CDC_UART_TX_=PA27_UART7_RXD, EDBG_CDC_UART_RX, ID1, ID4, EDBG_ADC0, EDBG_DGI_SDA, EDBG_DGI_SCL, EDBG_DGI_GPIO3=PB14_GPIO
Power Supply = schematic 3. Power Supply, on sheet TOP: TARGET_VOLTAGE=EDBG_ADC0, VBUS_HOST_EN=TARGET_USB_ID

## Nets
1V8: C1.2 C3.1 C4.1 C6.1 C7.1 C9.1 C11.1 C12.1 C22.1 R20.1 R23.2 R24.1 R25.1 R27.1 R28.1 U1.8(VDDIO) U1.13(VDD) U2.8(VDDIO) U2.13(VDD) U3.8(VDD) U4.5(RESV) U4.6(RESV) U4.10(VDD) U7.1(VL) U8.1(VL) U9.5(OUT)
GND: C1.1 C2.2 C3.2 C4.2 C5.2 C6.2 C7.2 C8.1 C9.2 C10.1 C11.2 C12.2 C13.2 C14.2 C15.2 C16.2 C17.2 C18.2 C20.2 C21.1 C22.2 C100.2 C101.2 C300.2 C301.2 C302.2 C303.2 C304.2 C305.2 C307.2 C308.2 C309.2 C310.2 C311.2 C312.2 C314.2 C400.2 C401.2 C402.2 C403.2 C500.2 C501.2 C502.2 C504.2 C505.2 C506.2 C507.2 C508.2 C509.2 C510.2 C511.2 C512.2 C513.2 C514.2 C515.2 CN1.11 CN1.13 CN2.8(9) CN2.10 CN3.7(4) CN3.9(5) CN4.8(9) CN4.10 CN5.7(4) CN5.9(5) CN6.5(GND) CN6.6/2(NC3) CN6.7/2(NC4) CN6.8/2(NC2) CN6.9/2(NC1) CN7.2 CN8.4 CN8.6 CN8.8 CN8.10 CN8.12 CN8.14 CN8.16 CN8.18 CN8.20 CN9.2(GND) CN9.10(GND) D301.1 D502.1 J200.2/2(2) J200.19/2(19) J201.8 J203.2/2(2) J203.19/2(19) J204.3/2(3) J204.5/2(5) J204.9/2(9) J301.5(GND) J301.6/2(NC3) J301.7/2(NC4) J301.8/2(NC2) J301.9/2(NC1) J500.5(GND) J500.6/2(NC3) J500.7/2(NC4) J500.8/2(NC2) J500.9/2(NC1) MT1.1 MT2.1 MT3.1 MT4.1 Q500.1(S2) Q500.4(S1) R4.1 R9.2 R19.1 R100.2 R113.1 R312.1 R317.2 R506.1 R515.1 SW300.1 SW300.2 SW301.1 SW301.2 TP500.1 U1.1(BVPP) U1.18(VSS) U1.20(GVPP) U2.18(GND) U2.20(RESV) U3.1(GND) U3.2(RESV) U3.5(RESV) U3.6(RESV) U3.7(GND) U4.1(RESV) U4.3(RESV) U4.8(GND) U4.9(GND) U5.7(GND) U5.18(GND) U5.21(GND) U5.25(AGND) U5.26(TEST) U6.2(GND) U7.7(GND) U8.7(GND) U9.2(GND) U100.7(GND) U100.9(GND) U102.2(GND) U300.13(GND) U300.29(GND) U300.53(GND) U500.B10(GNDPLL) U500.C3(GNDIO) U500.C8(GNDIO) U500.E2(GNDIO) U500.E6(GNDIO) U500.F5(GNDIO) U500.F10(GNDCORE) U500.H3(GNDIO) U500.H8(GNDANA) XC400.3
VBAT: C18.1 CN7.1 J1.1 U6.5(BAT)
VCC_CHEETAH_P5V0: CN9.4(5V) CN9.6(5V) J4.1
VCC_EDBG_P3V3: C509.1 C510.1 C511.1 C512.1 C513.1 C514.1 C515.1 D500.2(ANODE) D501.2(ANODE) L501.1 R500.2 R502.2 R503.2 R517.1 TP507.1 U500.B5(VDDIO) U500.B6(VDDIO) U500.D9(VDDIN) U500.D10(VDDIN) U500.E5(VDDIO) U500.F2(VDDIO) U500.F6(VDDIO) U500.J5(VDDIO)
VCC_EDBG_USB_P5V0: C508.1 J1.3 L500.2 U500.A10(USB_VBUS)
VCC_FTDI_USB_P5V0: C13.1 C14.1 CN6.1(VBUS) D1.1 J1.5 J4.2 U5.20(VCC)
VCC_MCU_P3V3: C301.1 C307.1 C308.1 C309.1 C310.1 C311.1 C314.1 CN8.1 CN8.2 J204.1/2(1) R3.1 R13.1 R14.1 R18.2 R21.1 R114.2 R318.2 R319.2 R320.2 U300.1(VDDIO) U300.26(VDDUSB) U300.27(VDDIO) U300.28(VREFP) U300.31(VDDIO) U300.32(VDDIO) U300.64(VDDIO)
VCC_P3V3: C100.1 R102.1 R111.1 R517.2 U100.5(VOUT)
VCC_P5V0: C17.1 C101.1 CN1.19 D2.1 J1.2 J1.4 J1.6 J1.8 U6.4(DC) U100.1(EN) U100.3(VIN) U102.5(IN)
VCC_TARGET_P3V3: C8.2 C10.2 C15.1 C20.1 C21.2 CN2.9(5) CN3.10 J5.1 J6.2 J200.20/2(20) J201.7 J203.20/2(20) J300.2/2(2) R10.1 R11.2 R109.1 R110.2 R111.2 R112.2 R114.1 R200.2 R201.2 R202.2 R203.2 R300.2 R301.2 R302.2 R303.2 R305.2 R308.2 U5.4(VCCIO) U7.14(VCC) U8.14(VCC) U9.1(Vin) U9.3(EN)
VCC_TARGET_USB_P5V0: D301.4 J1.7 J301.1(VBUS) R311.2 U102.1(OUT)
VDD_TDK: CN5.10 J5.2 R10.2
VDDCORE_P1V2: C302.1 C303.1 C304.1 C305.1 U300.9(VDDCORE) U300.30(VDDOUT) U300.45(VDDCORE)
VDDIO_TDK: CN4.9(5) J6.1 R11.1
DB_CS: CN1.4 CN5.8(9) CN9.9(SS1) R15.2 R21.2
EDBG MCU/DGI_GPIO0: R509.2 U500.F8(PA08)
EDBG MCU/DGI_GPIO1: R510.2 U500.D8(PA09)
EDBG MCU/DGI_GPIO2: R511.2 U500.C10(PA10)
EDBG MCU/DGI_GPIO3: R512.2 U500.C9(PA11)
EDBG MCU/EDBG_CDC_UART_TX: R507.2 U500.E9(PA04)
EDBG MCU/EDBG_DGI_USART_CLK: R518.2 U500.H10(PA07/PA19)
EDBG MCU/EDBG_DGI_USART_TX: R508.2 U500.E8(PA06/PA13)
EDBG MCU/EDBG_FORCE_BOOT: TP501.1 U500.H9(PA20/PX18)
EDBG MCU/EDBG_JTAG_TCK: TP502.1 U500.K9(TCK)
EDBG MCU/EDBG_JTAG_TDI: TP503.1 U500.K8(TDI)
EDBG MCU/EDBG_JTAG_TDO: TP504.1 U500.J8(TDO)
EDBG MCU/EDBG_JTAG_TMS: TP505.1 U500.H7(TMS)
EDBG MCU/EDBG_RESET_N: TP506.1 U500.J9(RESET_N)
EDBG MCU/EDBG_USB_FS_N: R513.2 U500.B9(DMFS)
EDBG MCU/EDBG_USB_FS_P: R514.2 U500.B8(DPFS)
EDBG MCU/EDBG_USB_HS_N: D502.3 J500.2(DM) R513.1 U500.A9(DMHS)
EDBG MCU/EDBG_USB_HS_P: D502.2 J500.3(DP) R514.1 U500.A8(DPHS)
EDBG MCU/POWER_LED_CTRL: Q500.2(G2) R503.1 U500.K4(PX15/PX32)
EDBG MCU/STATUS_LED_CTRL: Q500.5(G1) R506.2 U500.F1(PX19/PX59)
EDBG MCU/XIN0: C500.1 U500.A5(PC02) XC500.1
EDBG MCU/XOUT0: C501.1 U500.A6(PC03) XC500.3
EDBG_ADC0: R112.1 R113.2 U500.K10(PA21/PX22)
EDBG_CDC_UART_RX: U300.21(PA28) U500.F9(PA03)
EDBG_DGI_SCL: J200.12/2(12) J203.12/2(12) R302.1 U300.47(PB11) U500.F7(PA26/PB05)
EDBG_DGI_SDA: J200.11/2(11) J203.11/2(11) R303.1 U300.46(PB10) U500.G7(PA12/PA25)
EDBG_DGI_USART_RX: R315.1 U500.G9(PA05)
ID1: J200.1/2(1) R502.1 U500.A1(PA28)
ID4: J203.1/2(1) R500.1 U500.D3(PX13)
INVN Sensor//CS_1V8: R23.1 U1.22(nCS) U2.22(nCS) U7.2(IO-VL1)
INVN Sensor//Tri-State: R20.2 U7.8(/Tri-State) U8.8(/Tri-State)
INVN Sensor/AUXCL_1V8: R28.2 U1.7(AUX_CL) U2.7(AUX_CL) U8.3(IO-VL2)
INVN Sensor/AUXDA_1V8: R27.2 U1.6(AUX_DA) U2.21(AUX_DA) U8.4(IO-VL3)
INVN Sensor/FSYNC_1V8: R19.2 U1.11(FSYNC) U2.11(FSYNC)
INVN Sensor/INT1_1V8: U1.12(INT) U2.12(INT1) U8.5(IO-VL4)
INVN Sensor/INT2_1V8: U1.19(DRDY) U2.19(INT2) U8.2(IO-VL1)
INVN Sensor/MISO/AD0_1V8: U1.9(SDO/AD0) U2.9(SDO_AD0) U7.5(IO-VL4)
INVN Sensor/MOSI/SDA_1V8: R24.2 U1.24(SDA/SDI) U2.24(SDA_SDI) U3.3(SDA) U4.4(SDA) U7.3(IO-VL2)
INVN Sensor/SCLK/SCL_1V8: R25.2 U1.23(SCL/SCLK) U2.23(SCL_SCLK) U3.4(SCL) U4.2(SCL) U7.4(IO-VL3)
INVN Sensor/SN_MISO/AD0_DBEVB: CN1.20 CN4.7(4) CN9.5(MISO) J7.1
Main MCU/JTAGSEL: TP302.1 U300.63(JTAGSEL)
Main MCU/PA00_TIOA0: J200.7/2(7) U300.6(PA00)
Main MCU/PA01_TIOB0: J201.2 R203.1 U300.7(PA01)
Main MCU/PA03_TWD3: J201.5 R201.1 U300.5(PA03)
Main MCU/PA04_TWCK3: J201.6 R202.1 U300.4(PA04)
Main MCU/PA07_XIN32: C400.1 U300.11(XIN32/PA07) XC400.2
Main MCU/PA08_XOUT32: C401.1 R7.2 U300.12(XOUT32/PA08)
Main MCU/PA16_WKUP7: J201.3 R200.1 U300.18(PA16)
Main MCU/PA17_AD0: J200.3/2(3) U300.33(PA17)
Main MCU/PA18_AD1: J200.4/2(4) U300.34(PA18)
Main MCU/PA19_AD2: R1.2 U300.35(PA19)
Main MCU/PA23_TIOA1: J200.8/2(8) U300.23(PA23)
Main MCU/PA29_GPIO: J200.10/2(10) U300.20(PA29)
Main MCU/PA31_GPIO: J203.5/2(5) U300.16(PA31)
Main MCU/PB00_UART_TXD6: R315.2 U300.37(PB00)
Main MCU/PB01_UART_RXD6: R316.2 U300.38(PB01)
Main MCU/PB02_AD6: R314.2 U300.39(PB02)
Main MCU/PB04_GPIO_TDI: CN8.5 R2.2 R14.2 U300.62(TDI/PB04)
Main MCU/PB08_XOUT: C403.1 R8.2 R306.2 U300.59(PB08)
Main MCU/PB09_XIN: C402.1 R307.2 U300.60(PB09) XC401.3
Main MCU/PB12_ERASE: J300.1/2(1) U300.3(PB12)
Main MCU/TARGET_USB_N: D301.3 J301.2(DM) U300.25(PA21)
Main MCU/TARGET_USB_P: D301.2 J301.3(DP) U300.24(PA22)
Main MCU/TST: R317.1 U300.10(TEST)
PA02_WKUP2: C300.1 R304.2 R509.1 U300.61(PA02)
PA05_SPI5_NPCS1: R22.1 U300.8(PA05)
PA06_GPIO: D300.1(CATHODE) R510.1 U300.17(PA06)
PA09_UART_RXD0: J3.1 J200.13/2(13) U300.49(PA09)
PA10_UART_TXD0: J3.3 J200.14/2(14) U300.48(PA10)
PA11_SPI5_NPCS0: J200.15/2(15) R15.1 U300.44(PA11)
PA12_SPI5_MISO: J7.2 J200.17/2(17) R4.2 R18.1 U7.10(IO-VCC4) U300.43(PA12)
PA13_SPI5_MOSI: J200.16/2(16) R17.1 U300.42(PA13)
PA14_SPI5_CLK: J200.18/2(18) R16.1 U300.41(PA14)
PA15_GPIO: CN2.1 U300.22(PA15)
PA20_AD3: CN1.6 CN5.2(6) U300.36(PA20)
PA24_WKUP11: J200.9/2(9) R511.1 U300.58(PA24)
PA25_GPIO_CTS0: J3.7 J200.6/2(6) U300.56(PA25)
PA26_GPIO_RTS0: J3.5 J200.5/2(5) U300.52(PA26)
PA27_UART7_RXD: R507.1 U300.51(PA27)
PA30_GPIO: CN1.3 CN4.1 U300.19(PA30)
PB03_WKUP13: U8.10(IO-VCC4) U300.40(PB03)
PB05_TRACESWO: CN8.13 J204.6/2(6) R318.1 U300.50(TDO/TRACESWO/PB05) U500.A3(PB04)
PB06_SWDIO: CN8.7 J204.2/2(2) R319.1 U300.54(TMS/SWDIO/PB06) U500.C5(PB09)
PB07_SWCLK: CN8.9 CN8.11 J204.4/2(4) R320.1 U300.55(TCK/SWCLK/PB07) U500.D6(PB07)
PB08_TWD6: J2.1 J2.7 R301.1 R306.1
PB09_TWCK6: J2.3 J2.5 R300.1 R307.1
PB13_USART6_CLK: R518.1 U300.57(PB13)
PB14_GPIO: J203.9/2(9) R512.1 U300.15(PB14)
PB15_GPIO: U8.13(IO-VCC1) U300.14(PB15)
SN_CS: R3.2 R22.2 U7.13(IO-VCC1)
SN_MOSI/SDA: CN1.18 CN3.4(7) CN5.4(7) CN9.8(MOSI) J2.2 R17.2 U7.12(IO-VCC2)
SN_SCLK/SCL: CN1.16 CN3.6(8) CN5.6(8) CN9.7(SCLK) J2.4 R16.2 U7.11(IO-VCC3)
TARGET_RESET: CN8.15 J201.4 J204.10/2(10) R309.2 U300.2(RESETN) U500.B4(PA29) U500.H2(PX21)
TARGET_USB_ID: J301.4(ID) R110.1 R314.1 U102.4(EN)
EDBG MCU/N135144: C505.1 C506.1 U500.E10(VDDCORE)
EDBG MCU/N16779126: C507.1 D502.4 J500.1(VBUS) L500.1
EDBG MCU/N16781968: C502.1 R515.2 U500.C7(USB_VBIAS)
EDBG MCU/N16782463: C504.1 L501.2 U500.J6(VDDANA)
EDBG MCU/N16785895: D500.1(CATHODE) R504.2
EDBG MCU/N16785898: Q500.6(D2) R504.1
EDBG MCU/N16785926: Q500.3(D1) R505.1
EDBG MCU/N16785929: D501.1(CATHODE) R505.2
INVN Sensor/N99493: C16.1 U5.17(3V3OUT)
INVN Sensor/N99539: D1.2 R9.1
INVN Sensor/N99547: CN6.2(DM) U5.16(USBDM)
INVN Sensor/N99597: CN6.3(DP) U5.15(USBDP)
INVN Sensor/N99625: R5.1 U5.3(RTS#)
INVN Sensor/N99637: R6.1 U5.11(CTS#)
INVN Sensor/N16828908: C2.1 U1.10(REGOUT)
INVN Sensor/N16829571: C5.1 U2.10(REGOUT)
Main MCU/N13191: R310.1 SW301.3 SW301.4
Main MCU/N13215: C312.1 R308.1 R309.1 R310.2
Main MCU/N33506: R304.1 SW300.3 SW300.4
Main MCU/N34468: D300.2(ANODE) R305.1
Main MCU/N16775763: R1.1 R2.1 R311.1 R312.2
Main MCU/N16797737: R7.1 XC400.1
Main MCU/N16801857: R8.1 XC401.1
Main MCU/N16806419: CN8.3 R13.2
N96210: CN2.3(2) CN4.3(2) J2.8 U8.11(IO-VCC3)
N96214: CN2.5(3) CN4.5(3) J2.6 U8.12(IO-VCC2)
N105398: R316.1 R508.1
N115089: J3.2 U5.1(TXD)
N115091: J3.4 U5.5(RXD)
N115093: J3.6 R6.2
N115095: J3.8 R5.2
Power Supply/N16792425: R109.2 U102.3(FAULT)
Power Supply/N16793474: R100.1 R102.2 U100.8(ADJ/BYP)
Power Supply/N16865076: R12.2 U6.3(CHG#)
Power Supply/N16865598: D2.2 R12.1

Not connected (* = marked no-connect by the designer): CN1 1* 2 5* 7* 8* 9* 10* 12* 14* 15* 17*; CN2 2(6)* 4(7)* 6(8)* 7(4)*; CN3 1* 2(6)* 3(2)* 5(3)* 8(9)*; CN4 2(6)* 4(7)* 6(8)*; CN5 1* 3(2)* 5(3)*; CN6 4(ID)*; CN8 17* 19*; CN9 1(SS2)* 3(SS3)*; J201 1*; J203 3/2(3) 4/2(4) 6/2(6) 7/2(7) 8/2(8) 10/2(10) 13/2(13) 14/2(14) 15/2(15) 16/2(16) 17/2(17) 18/2(18); J204 7/2(7) 8/2(8); J500 4(ID)*; U1 2(NC1)* 3(NC2)* 4(NC3)* 5(NC4)* 14(NC5)* 15(NC6)* 16(NC7)* 17(NC8)* 21(ESDA_DUP)*; U2 1(NC)* 2(NC)* 3(NC)* 4(NC)* 5(NC)* 6(NC)* 14(NC)* 15(NC)* 16(NC)* 17(NC)*; U4 7(RESV)*; U5 2(DTR#)* 6(RI#)* 8(NC)* 9(DSR#)* 10(DCD#)* 12(CBUS4)* 13(CBUS2)* 14(CBUS3)* 19(RESET#)* 22(CBUS1)* 23(CBUS0)* 24(NC)* 27(OSCI)* 28(OSCO)*; U6 1(USB); U7 6(NC)* 9(NC)*; U8 6(NC)* 9(NC)*; U9 4(NC)*; U100 2(NC)* 4(NC)* 6(NC)*; U500 A2(PA27) A4(PA30) A7(PC05) B1(PB00) B2(PB01) B3(PB02) B7(PC04) C1(PB11) C2(PA31) C4(PB03) C6(PB08) D1(PX12) D2(PX10) D4(PX16/PX53) D5(PB10) D7(PB06) E1(PA02/PX47) E3(PX08) E4(PX09) E7(PA16) F3(PX06) F4(PX07) G1(PX05) G2(PX01) G3(PX02) G4(PX00) G5(PX30) G6(PA23/PX46) G8(PA00/PA18) G10(PA01/PA17) H1(PX04) H4(PX25) H5(PX31) H6(PA22/PX20) J1(PX03) J2(PX24) J3(PX26) J4(PX29) J7(PA15/PX45) J10(PA24/PX17) K1(PX23) K2(PX27) K3(PX28) K5(PC00/PX14) K6(PC01) K7(PA14/PX11)

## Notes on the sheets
sheet 3
- EDBG Power and Status LEDs
- Green
- Yellow
- Current limiters
- 10mA @ 3.3V
- PROG USB
sheet 4
- QFN24_4x4
- Other Sensor DB
- INV Sensor DB
- QFN 3x3
- Connect to Cheetah
  (when use Cheetah, remove R15/16/17/18)
- 300mA
- Connect to
  Sensor EVB
- UART to USB
- Short:DB/EVB=SPI
  Open:DB/DVB=I2C
- I2C Slave Address = 0x63
- I2C Slave Address = 0x63
sheet 5
- NCHG
- IRQ
- RESET
- I2C_SCL
- I2C_SDA
- {
- SWD
- {
- DGI_GPIO
- {
- DGI_USART
- {
- DGI_TWI
- {
- CDC_UART
- USER_LED
- USER_BUTTON
- 12.0MHz
- 22pF
- 22pF
- Target USB
- PA21_USB_N
- PA22_USB_P
- Cortex Debug Connector for
- External programmer/debugger
sheet 6
- 500mA
- Power
  multiplexer
- 3.3V linear regulator
- OHCI Current
  Limitation
- Battery
  Charger
- 100mA
- 280mA
